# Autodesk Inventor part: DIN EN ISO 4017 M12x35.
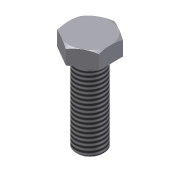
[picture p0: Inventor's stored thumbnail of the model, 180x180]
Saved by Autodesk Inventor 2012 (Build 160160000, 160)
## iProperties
Created: 2001-01
Part Number: DIN EN ISO 4017 M12x35.
Material: Steel, Mild
Document SubType Name: Modeling
Description: Sechskantschraube DIN EN ISO 4017 - M12x35.
Standard: DIN EN ISO 4017
Density: 7.86 g/cm^3
Company: CAD-Verlag
+MSCProtocol1+ProtocolID: P00040924055603081
+MSCProtocol2+Protocol: P00040924055603081<@PID>[Version]<@EL>Version=2.2<@EL>[Data]<@EL>mass=0.0475776{kg<@EL>b=31.5{mm<@EL>c=0.6{mm<@EL>dw=17{mm<@EL>r=0.6{mm<@EL>s=18{mm<@EL>d=12{mm<
Control State: 0
Master: False
Checked Out: False
Shininess: 20.0
Length Units: 11269
Angle Units: 11279
Time Units: 11290
Mass Units: 11283
Length Display Precision: 3
Angle Display Precision: 2
BOM1: Sechskantschraube
BOM2: M12x35
BOM3: DIN EN ISO 4017
d28: 0,000 mm
Density: 7.859999999999999
Volumn: 5.59798751986722
Area: 24.439342304675858
PropertySet Name: Model Information
Author: Jürgen Kronas
Revision Number: 1
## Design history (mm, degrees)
node "WorkPlane1"
node "Sketch1"
node "WorkPoint1"
extrude "ExtrusionBlind1" new body distance "d2" = 35 (= prf_l); taper "d3" = 0 deg
  node "Sketch2" dims "d1" = 12 (= prf_d)
chamfer "Chamfer1" distance "d4" = 0.875 (= msp_z); stored, may be unused: second distance "d5" = 0.875 (= msp_z), angle "d31" = 45 deg
node "WorkAxis1"
sketch "Sketch3" dims "d8" = 17 (= prf_dw)
  geometry: C1 r 6 at (0, 0) reference
  constraints: 1 other
extrude "ExtrusionBlind2" join sketch "Sketch3" distance "d9" = 0.6 (= prf_c); taper "d10" = 0 deg
sketch "Sketch4" dims "d13" = 18 (= prf_s)
  geometry: L1 (-9, 5.196)-(-9, -5.196); L2 (0, 10.392)-(-9, 5.196); L3 (9, 5.196)-(0, 10.392); L4 (9, -5.196)-(9, 5.196); L5 (0, -10.392)-(9, -5.196); L6 (-9, -5.196)-(0, -10.392); C1 r 8.5 at (0, 0) reference; C2 r 6 at (0, 0) reference; C3 r 5.125 at (0, 0) reference
  constraints: 12 end point, 4 vertical, 2 parallel, 7 other
extrude "ExtrusionBlind3" join sketch "Sketch4" distance "d14" = 6.9 (= -prf_c + prf_k); taper "d15" = 0 deg
sketch "Sketch5"
  geometry: L1 (-10.392, 6.696)-(-9, 7.5); L2 (0, -50.981)-(0, 0.981); L3 (0, -62.677)-(0, 19.196) reference; L4 (-9, 7.5)-(-10.392, 7.5); L5 (-10.392, 7.5)-(-10.392, 6.696); L6 (-10.392, 0.6)-(-10.392, 7.5) reference
  constraints: 8 end point, 2 perpendicular
  dimensions: "d20" = 0 distance between parallel lines of L6 L5; "d21" = 0 distance from line of L6.end L4; "d22" = 9 distance from line of L3 L1.end (= 0.5 x prf_s); "d23" = 60 deg angle of L6 L1
revolve "RevolutionFull1" sketch "Sketch5" stored, may be unused: angle "d18" = 360 deg
fillet "Fillet1" dims "d19" = 0.6 (= prf_r)
feature "Ms_Thread" dims "d25" = 0, "prf_b" = 31.5
node "MSC_A1"
node "MSC_PF1"
node "MSC_PT1"
node "Volumenkörper1"
node "Volumenkörpern"
node "Oberflächenkörpern"
other parameters: "prf_p" = 1.75 [user parameter; used in 1 equation term], "prf_l" = 35 [user parameter; used in 1 equation term], "prf_k" = 7.5 [user parameter; used in 1 equation term], "prf_d" = 12 [user parameter; used in 1 equation term], "prf_s" = 18 [user parameter; used in 2 equation terms], "prf_r" = 0.6 [user parameter; used in 1 equation term], "prf_dw" = 17 [user parameter; used in 1 equation term], "prf_c" = 0.6 [user parameter; used in 2 equation terms], "msp_z" = 0.875 (= 0.5 x prf_p) [user parameter; used in 2 equation terms], "d6" = 0, "d7" = 15 (derived), "d11" = 0, "d12" = 17 (derived), "d16" = 30 deg (derived), "d28" = 0, "d29" = 0, "d30" = 0
